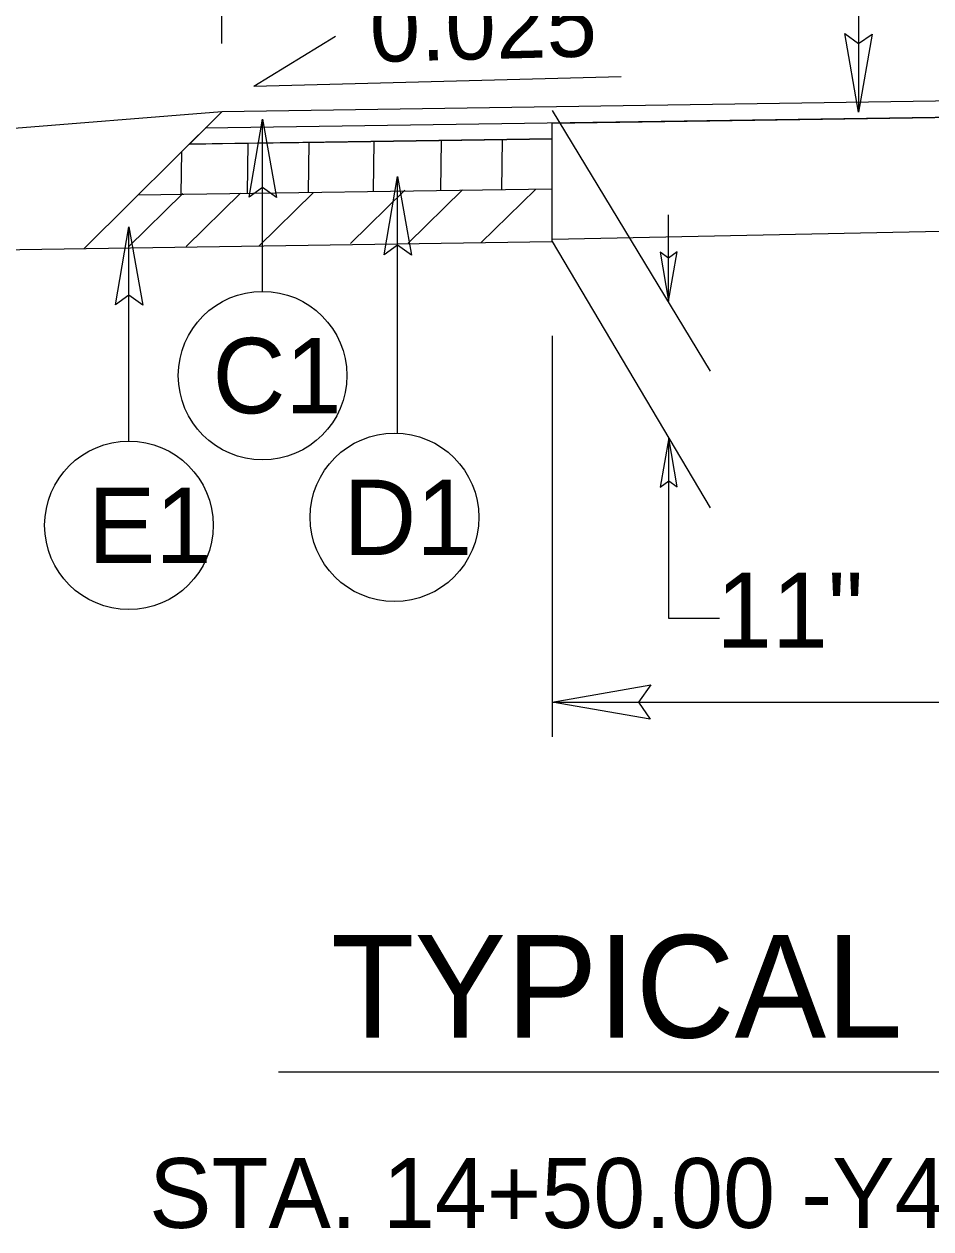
# Model space of a CAD drawing. Extents: x 2176156 to 2177167, y 76401 to 76644.
# Drawn here: x 2176304.2 to 2176318.14, y 76544.04 to 76562.57 of the extents above; entities that cross this region are included whole.
import ezdxf

# ---------------------------------------------------------------- set-up
doc = ezdxf.new("R2010")
doc.units = 0
for name, color, linetype in [('Exist Building', 7, 'Continuous'), ('Exist Building Metal Canopy', 7, 'Continuous'), ('Exist Roads Curbs', 7, 'Continuous'), ('Exist Roads EOP Other', 7, 'Continuous'), ('Exist Roads Soil', 7, 'Continuous'), ('Exist Utilities Other Pole CELL', 7, 'Continuous'), ('Exist Vegetation Woods Line', 7, 'Continuous'), ('Model Boundary Lines Text', 7, 'Continuous'), ('Old_Level_1', 7, 'Continuous'), ('Old_Level_3', 7, 'Continuous'), ('Prop North Arrow NAD83 for Plan Sheets CELL', 7, 'Continuous'), ('Sheet Plan CELL', 7, 'Continuous')]:
    doc.layers.add(name, color=color, linetype=linetype)

msp = doc.modelspace()

# ---------------------------------------------------------------- linework, layer by layer
at = {"layer": 'Exist Building'}
for p, q in [((2176312.319, 76559.229), (2176312.319, 76561.052)), ((2176291.193, 76558.915), (2176312.319, 76559.229))]:
    msp.add_line(p, q, dxfattribs=at)
at = {"layer": 'Exist Roads Curbs'}
for p, q in [((2176319.239, 76561.404), (2176307.239, 76561.226)), ((2176319.239, 76561.404), (2176307.239, 76561.226)), ((2176307.239, 76561.226), (2176306.739, 76560.729)), ((2176321.097, 76561.182), (2176306.983, 76560.972)), ((2176306.739, 76560.729), (2176307.25, 76560.736))]:
    msp.add_line(p, q, dxfattribs=at)
msp.add_lwpolyline([(2176307.25, 76560.736), (2176308.813, 76560.76), (2176309.529, 76560.77), (2176310.927, 76560.791), (2176312.319, 76560.812), (2176312.319, 76561.052), (2176319.239, 76561.154)], dxfattribs=at)
at = {"layer": 'Exist Roads EOP Other'}
msp.add_line((2176307.239, 76561.226), (2176297.239, 76560.426), dxfattribs=at)
at = {"layer": 'Exist Roads Soil'}
for p, q in [((2176307.239, 76561.226), (2176305.122, 76559.122)), ((2176312.319, 76560.812), (2176306.739, 76560.729)), ((2176312.307, 76560.035), (2176305.946, 76559.941))]:
    msp.add_line(p, q, dxfattribs=at)
at = {"layer": 'Exist Utilities Other Pole CELL'}
for q in [(2176308.987, 76562.391), (2176313.377, 76561.768)]:
    msp.add_line((2176307.731, 76561.621), q, dxfattribs=at)
at = {"layer": 'Model Boundary Lines Text'}
for p, q in [((2176309.57, 76560.006), (2176309.581, 76560.771)), ((2176310.603, 76560.019), (2176310.614, 76560.786)), ((2176311.543, 76560.026), (2176311.554, 76560.8)), ((2176306.612, 76559.953), (2176306.622, 76560.613)), ((2176307.632, 76559.974), (2176307.643, 76560.742)), ((2176308.572, 76559.982), (2176308.583, 76560.756)), ((2176309.217, 76559.2), (2176310.052, 76560.019)), ((2176310.101, 76559.204), (2176310.937, 76560.023)), ((2176311.22, 76559.208), (2176312.061, 76560.032)), ((2176305.803, 76559.15), (2176306.639, 76559.969)), ((2176306.689, 76559.155), (2176307.525, 76559.974)), ((2176307.809, 76559.159), (2176308.644, 76559.978)), ((2176308.108, 76546.457), (2176335.43, 76546.457))]:
    msp.add_line(p, q, dxfattribs=at)
at = {"layer": 'Old_Level_1'}
for points in [[(2176313.975, 76559.066), (2176314.107, 76558.312), (2176314.239, 76559.071), (2176314.105, 76558.975)], [(2176314.24, 76555.456), (2176314.108, 76556.21), (2176313.976, 76555.451), (2176314.11, 76555.548)], [(2176313.826, 76551.883), (2176312.317, 76552.143), (2176313.835, 76552.411), (2176313.642, 76552.143)]]:
    msp.add_lwpolyline(points, close=True, dxfattribs=at)
at = {"layer": 'Old_Level_3'}
for p, q in [((2176307.239, 76562.277), (2176307.239, 76575.463)), ((2176312.319, 76561.245), (2176314.744, 76557.237)), ((2176314.107, 76558.312), (2176314.107, 76559.64)), ((2176312.319, 76559.23), (2176314.745, 76555.135)), ((2176312.317, 76557.778), (2176312.317, 76551.614)), ((2176314.108, 76553.434), (2176314.108, 76556.21)), ((2176314.888, 76553.434), (2176314.108, 76553.434)), ((2176312.317, 76552.143), (2176338.626, 76552.143))]:
    msp.add_line(p, q, dxfattribs=at)
at = {"layer": 'Prop North Arrow NAD83 for Plan Sheets CELL'}
for p, q in [((2176317.028, 76564.354), (2176317.028, 76561.221)), ((2176307.865, 76558.464), (2176307.865, 76561.114)), ((2176309.939, 76556.283), (2176309.939, 76560.228)), ((2176305.81, 76556.161), (2176305.81, 76559.457))]:
    msp.add_line(p, q, dxfattribs=at)
for points in [[(2176317.235, 76562.421), (2176317.028, 76561.221), (2176316.815, 76562.428), (2176317.028, 76562.274)], [(2176307.659, 76559.914), (2176307.865, 76561.114), (2176308.079, 76559.907), (2176307.865, 76560.06)], [(2176309.732, 76559.028), (2176309.939, 76560.228), (2176310.152, 76559.022), (2176309.939, 76559.175)], [(2176305.603, 76558.257), (2176305.81, 76559.457), (2176306.023, 76558.25), (2176305.81, 76558.403)]]:
    msp.add_lwpolyline(points, close=True, dxfattribs=at)
for centre in [(2176307.865, 76557.168), (2176305.81, 76554.865), (2176309.893, 76554.988)]:
    msp.add_circle(centre, 1.296, dxfattribs=at)
at = {"layer": 'Sheet Plan CELL'}
msp.add_line((2176312.319, 76559.266), (2176321.769, 76559.462), dxfattribs=at)

# ---------------------------------------------------------------- texts
at = {"layer": 'Exist Building Metal Canopy'}
msp.add_text('TYPICAL SECTION NO.  6', height=1.5766, rotation=0, dxfattribs=at).set_placement((2176308.914, 76546.985))
at = {"layer": 'Exist Utilities Other Pole CELL'}
msp.add_text('0.025', height=1.0429, rotation=1.4932, dxfattribs=at).set_placement((2176309.525, 76561.99))
at = {"layer": 'Exist Vegetation Woods Line'}
msp.add_text('STA. 14+50.00 -Y4- TO STA. 18+03.30 -Y4-', height=1.0742, dxfattribs=at).set_placement((2176306.121, 76544.058))
at = {"layer": 'Prop North Arrow NAD83 for Plan Sheets CELL'}
for s, p in [('C1', (2176307.096, 76556.588)), ('E1', (2176305.182, 76554.285)), ('D1', (2176309.108, 76554.408))]:
    msp.add_text(s, height=1.16, rotation=0.0003, dxfattribs=at).set_placement(p)
msp.add_text('11"', height=1.1533, dxfattribs=at).set_placement((2176314.839, 76552.985))

doc.saveas('drawing.dxf')
